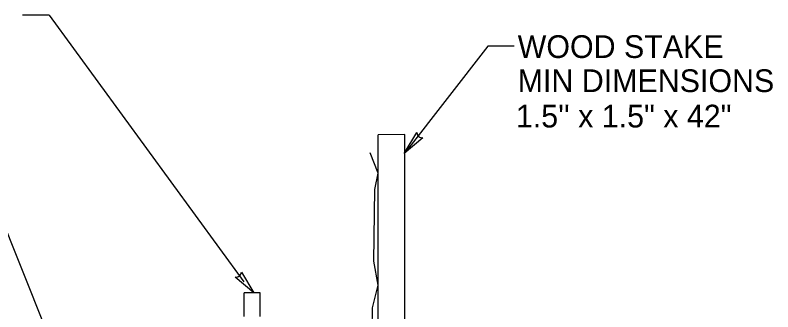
# Model space of a CAD drawing. Extents: x 0 to 2.83, y -0.06 to 1.83.
# Drawn here: x 0.7665 to 1.0583, y 0.5184 to 0.6326 of the extents above; entities that cross this region are included whole.
import ezdxf

# ---------------------------------------------------------------- set-up
doc = ezdxf.new("R2010")
doc.units = 0
for name, color, linetype in [('Edge_of_Truck_Apron', 7, 'Continuous'), ('Geotextile Fabric Fence', 7, 'Continuous'), ('Haybales', 7, 'Continuous'), ('Longitudinal Joint', 7, 'Continuous'), ('Wood Stakes', 7, 'Continuous')]:
    doc.layers.add(name, color=color, linetype=linetype)

msp = doc.modelspace()

# ---------------------------------------------------------------- linework, layer by layer
at = {"layer": 'Edge_of_Truck_Apron'}
for p, q in [((0.7795779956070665, 0.6326021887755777), (0.7693943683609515, 0.6326021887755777)), ((0.7795779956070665, 0.6326021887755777), (0.8545756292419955, 0.529943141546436)), ((0.9485326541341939, 0.6206040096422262), (0.91725790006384, 0.5804129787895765)), ((0.9587162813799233, 0.6206040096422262), (0.9485326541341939, 0.6206040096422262)), ((0.9163939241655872, 0.5794125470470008), (0.9212197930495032, 0.5873833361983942)), ((0.9163939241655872, 0.5794125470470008), (0.9212197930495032, 0.5873833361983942)), ((0.9235440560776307, 0.5853873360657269), (0.9163939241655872, 0.5794125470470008)), ((0.9235440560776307, 0.5853873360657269), (0.9163939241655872, 0.5794125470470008)), ((0.801867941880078, 0.45289653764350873), (0.7549279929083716, 0.5702043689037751)), ((0.858406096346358, 0.5257361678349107), (0.8512925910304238, 0.5317545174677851)), ((0.858406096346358, 0.5257361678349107), (0.8512925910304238, 0.5317545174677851)), ((0.8536290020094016, 0.53373628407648), (0.858406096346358, 0.5257361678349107)), ((0.8536290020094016, 0.53373628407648), (0.858406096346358, 0.5257361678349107))]:
    msp.add_line(p, q, dxfattribs=at)
for centre, radius, start, end in [((0.9233115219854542, 0.5874678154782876), 0.0020934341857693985, 182.31276239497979, 276.37744812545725), ((0.9233115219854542, 0.5874678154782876), 0.0020934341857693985, 182.31276239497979, 276.37744812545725), ((0.8515378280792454, 0.533833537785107), 0.0020934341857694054, 263.2725898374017, 357.3372755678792), ((0.8515378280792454, 0.533833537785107), 0.0020934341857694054, 263.2725898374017, 357.3372755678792)]:
    msp.add_arc(centre, radius, start, end, dxfattribs=at)
at = {"layer": 'Geotextile Fabric Fence'}
for p, q in [((0.9063095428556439, 0.5718335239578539), (0.9032469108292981, 0.5795963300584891)), ((0.9050844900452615, 0.565500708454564), (0.9063095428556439, 0.5718335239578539)), ((0.9046395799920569, 0.5379193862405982), (0.9050844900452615, 0.565500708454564)), ((0.906267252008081, 0.5286678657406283), (0.9046395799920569, 0.5379193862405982)), ((0.9040848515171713, 0.5199649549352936), (0.906267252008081, 0.5286678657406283)), ((0.9039973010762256, 0.49066305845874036), (0.9040848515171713, 0.5199649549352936))]:
    msp.add_line(p, q, dxfattribs=at)
at = {"layer": 'Haybales'}
for p, q in [((0.8608113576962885, 0.5257498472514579), (0.8547254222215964, 0.5257426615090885)), ((0.8547350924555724, 0.5165511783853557), (0.8547254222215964, 0.5257426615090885)), ((0.8608118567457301, 0.516640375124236), (0.8608113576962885, 0.5257498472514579))]:
    msp.add_line(p, q, dxfattribs=at)
at = {"layer": 'Longitudinal Joint'}
for p, q in [((0.7795779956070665, 0.6326021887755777), (0.7693943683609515, 0.6326021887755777)), ((0.9485326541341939, 0.6206040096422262), (0.91725790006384, 0.5804129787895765)), ((0.9587162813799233, 0.6206040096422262), (0.9485326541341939, 0.6206040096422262)), ((0.9062194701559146, 0.441201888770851), (0.906308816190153, 0.5865962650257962)), ((0.9166157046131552, 0.5866084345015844), (0.906308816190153, 0.5865962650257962)), ((0.9165336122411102, 0.44096324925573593), (0.9166157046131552, 0.5866084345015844)), ((0.9063095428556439, 0.5718335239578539), (0.9032469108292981, 0.5795963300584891)), ((0.9050844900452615, 0.565500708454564), (0.9063095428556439, 0.5718335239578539)), ((0.9046395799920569, 0.5379193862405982), (0.9050844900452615, 0.565500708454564)), ((0.906267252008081, 0.5286678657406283), (0.9046395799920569, 0.5379193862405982)), ((0.9040848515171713, 0.5199649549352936), (0.906267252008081, 0.5286678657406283)), ((0.8608113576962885, 0.5257498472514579), (0.8547254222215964, 0.5257426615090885)), ((0.8547350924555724, 0.5165511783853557), (0.8547254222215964, 0.5257426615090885)), ((0.8608118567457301, 0.516640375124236), (0.8608113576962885, 0.5257498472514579)), ((0.9039973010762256, 0.49066305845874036), (0.9040848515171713, 0.5199649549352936))]:
    msp.add_line(p, q, dxfattribs=at)
at = {"layer": 'Wood Stakes'}
for p, q in [((0.9062194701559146, 0.441201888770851), (0.906308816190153, 0.5865962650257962)), ((0.9166157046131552, 0.5866084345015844), (0.906308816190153, 0.5865962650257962)), ((0.9165336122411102, 0.44096324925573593), (0.9166157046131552, 0.5866084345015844))]:
    msp.add_line(p, q, dxfattribs=at)

# ---------------------------------------------------------------- texts
at = {"layer": 'Edge_of_Truck_Apron'}
for s, p in [('WOOD STAKE ', (0.9600497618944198, 0.6161203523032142)), ('MIN DIMENSIONS', (0.9600497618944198, 0.6029953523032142)), ('1.5\'\' x 1.5" x 42"', (0.9593671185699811, 0.5893760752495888))]:
    msp.add_text(s, height=0.008749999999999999, dxfattribs=at).set_placement(p)

doc.saveas('drawing.dxf')
